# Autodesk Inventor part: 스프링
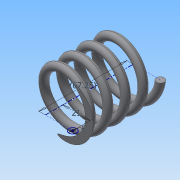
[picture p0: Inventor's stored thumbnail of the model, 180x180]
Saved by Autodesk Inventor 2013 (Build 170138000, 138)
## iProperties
Created: 2019-10
Part Number: 스프링
Material: 일반
Document SubType Name: Modeling
Designer: Administrator
Density: 1 g/cm^3
Mass: 17.498 g
Surface Area: 119.606 cm^2
Volume: 17.498 cm^3
Author: Administrator
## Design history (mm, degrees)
sketch "스케치1"
  geometry: L1 (0, 0)-(0, 67.25); L2 (0, 0)-(21, 0); L3 (0, 67.25)-(21, 67.25); C1 r 3 at (21, 0)
  constraints: 6 end point, 1 centre point, 1 coincident, 1 parallel, 1 perpendicular, 1 vertical
  dimensions: "d0" = 67.25 distance of L1.start L1.end (derived); "d1" = 21 distance of L1.start L2.end; "d2" = 6 diameter of C1
feature "코일1" sketch "스케치1" pitch "d3" = 10; turns "d5" = 5; dims "d4" = 67.25 (= d0), "d6" = 0, angle "d7" = 90 deg, angle "d8" = 90 deg, "d9" = 0, "d10" = 0
sketch "스케치2"
  geometry: L1 (31.074, 12.75)-(-28.926, 12.75); L2 (-28.926, 12.75)-(-28.926, 80); L3 (-28.926, 80)-(31.074, 80); L4 (31.074, 80)-(31.074, 12.75); 1 further point
  constraints: 8 end point, 2 parallel, 1 horizontal, 1 perpendicular
  dimensions: "d11" = 60 distance of L2.end L3.end; "d12" = 67.25 distance of L1.end L2.end (= d0)
extrude "돌출1" sketch "스케치2" stored distance "d13" = 0; taper "d14" = 0 deg
node "솔리드1"
